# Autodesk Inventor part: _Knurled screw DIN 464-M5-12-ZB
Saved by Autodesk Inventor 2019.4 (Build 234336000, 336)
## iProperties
Created: 2021-08
Part Number: _Knurled screw DIN 464-M5-12-ZB
Material: Generic
Document SubType Name: Modeling
Designer: Administrator
Density: 1 g/cm^3
Appearance: Default
Title: _Knurled screw DIN 464-M5-12-ZB
Author: Administrator
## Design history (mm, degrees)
feature "Body1"
body "Solid1"
